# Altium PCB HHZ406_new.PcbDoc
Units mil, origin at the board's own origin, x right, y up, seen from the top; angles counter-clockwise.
Board outline 1050 x 510 mil, 2 copper layers (Top Layer, Bottom Layer); 25 components, 14 nets, 71 pads, 20 vias.
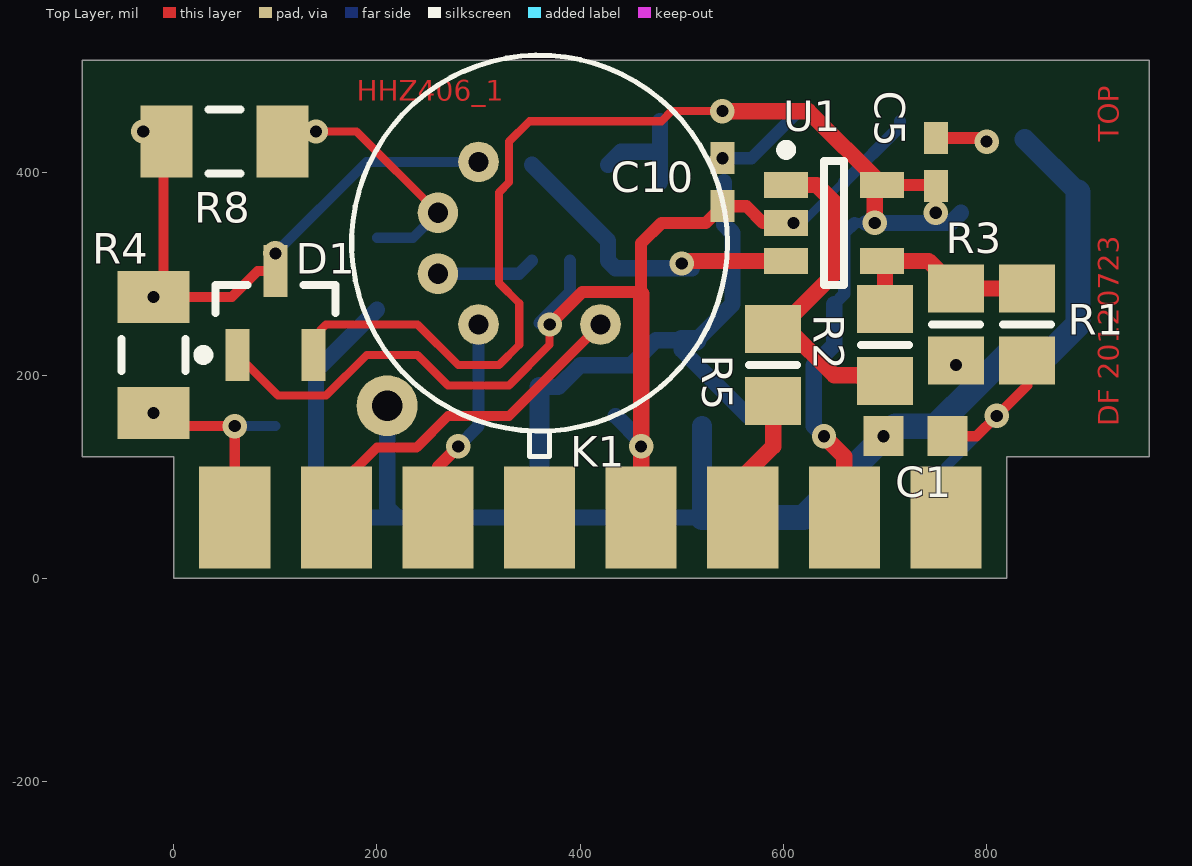
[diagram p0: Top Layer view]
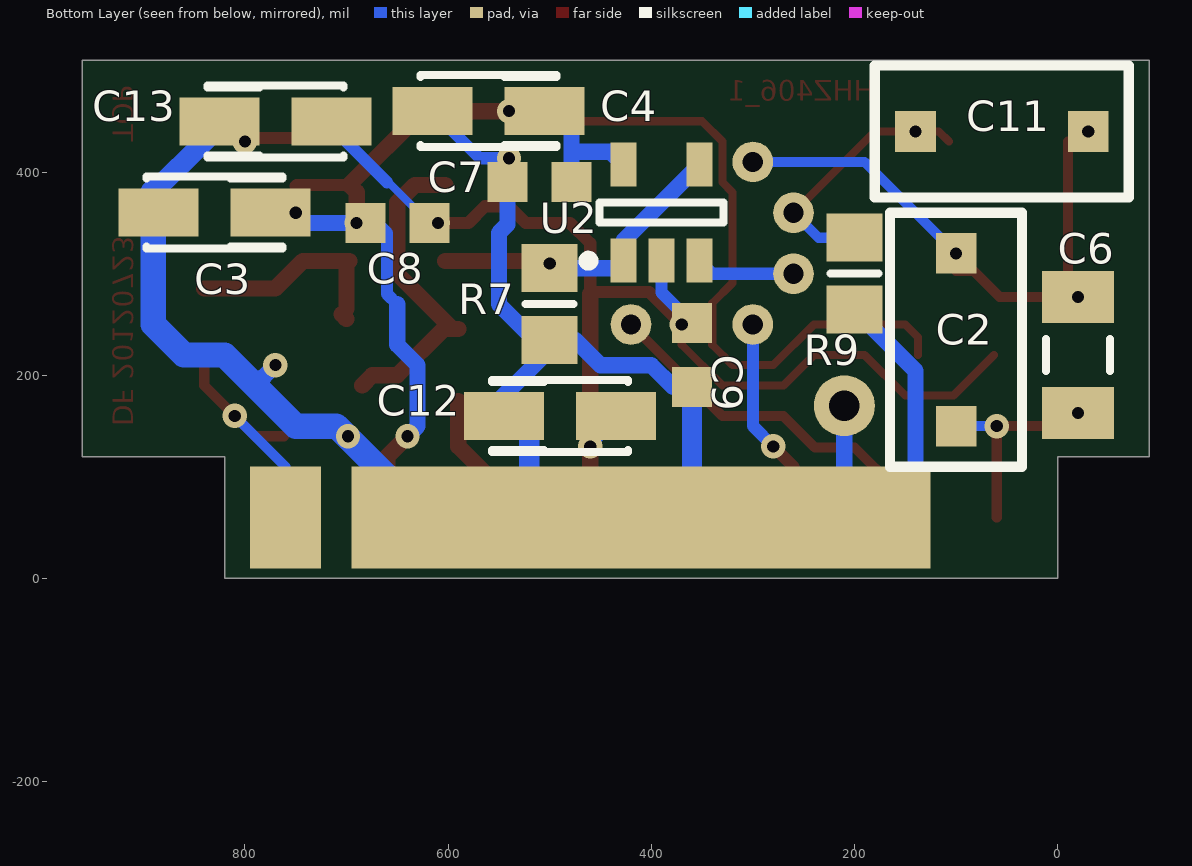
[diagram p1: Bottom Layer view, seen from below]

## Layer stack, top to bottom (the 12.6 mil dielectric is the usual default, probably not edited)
Top Layer: signal copper 1.4
Dielectric: dielectric 12.6, FR-4, Dk 4.8
Bottom Layer: signal copper 1.4

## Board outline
-90,120 -90,510 960,510 960,120 820,120 820,0 0,0 0,120

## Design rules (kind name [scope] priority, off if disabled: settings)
Clearance Clearance_PatchPad [All vs InPadClass('PatchPad')] p1: gap=25 // clearance to pads of within patch area
Clearance PolygonClearanceToNets [InPolygon vs InNet('GATE') OR InNet('U7_FB') OR InNet('U8_FB') OR InNet('U9_FB')] p2: gap=20 // Clearance to special nets, to minimize parasitic capacitance
Clearance PolygonClearance [InPolygon vs IsPad OR IsVia OR IsTrack OR InPoly] p3: gap=10 // Control the distance between polygon pour and other objects
Clearance [All] p4: gap=6
DiffPairsRouting [All] p1: maxlimit=393.7 minlimit=4.92 mostfreqgap=5.91 maxuncoupledlength=500
FabricationTestPointUsage FabricationTestPointUsage_1 [All] p1: valid=0 allowmultiple=FALSE
FabricationTestpoint FabricationTestpoint_1 [All] p1: side=3 testpointundercomponent=TRUE minsize=40 maxsize=100 preferedsize=60 minholesize=0 maxholesize=40 preferedholesize=32 testpointgrid=1 allowsidetop=TRUE allowsidebottom=TRUE usegrid=TRUE gridtolerance=0.01
HoleSize [All] p1: absolutevalues=TRUE maxlimit=236.22 minlimit=12 maxpercent=80.000 minpercent=20.000
HoleSize FabricationTestpoint [All] p2 off: absolutevalues=TRUE maxlimit=100 minlimit=1 maxpercent=80.000 minpercent=20.000
HoleSize FabricationTestPointUsage [All] p3 off: absolutevalues=TRUE maxlimit=100 minlimit=1 maxpercent=80.000 minpercent=20.000
MinimumAnnularRing [All] p1: minimumring=5.91
MinimumSolderMaskSliver [All] p1: minsoldermaskwidth=4
PlaneClearance [All] p1: clearance=19.68
PlaneConnect [All] p1: planeconnectstyle=Relief reliefexpansion=15.75 reliefentries=4 reliefconductorwidth=5.91 reliefairgap=5.91
PolygonConnect PolygonConnect_ViaOrSpecialPad [IsVia OR InPadClass('MountingHole') OR InPadClass('Screen1')] p1: connectstyle=Direct reliefconductorwidth=10 reliefentries=4 polygonreliefangle="90 Angle" // stitched vias and special pads should not have thermal relief
PolygonConnect [All] p2: connectstyle=Relief reliefconductorwidth=5.91 reliefentries=4 polygonreliefangle="90 Angle"
RoutingCorners [All] p1: cornerstyle=45-Degree minsetback=49.21 maxsetback=49.21
RoutingVias [All] p1: holewidth=12 width=24 viastyle="Through Hole" minholewidth=12 minwidth=24 maxholewidth=17.72 maxwidth=29.53
SilkToSilkClearance [All] p1 off: silktosilkclearance=10
SilkscreenOverComponentPads [All] p1 off: minsilkscreentomaskgap=10
SolderMaskExpansion SolderMaskExpansion_Via [IsVia] p1: expansion=0 // Via solder mask expansion
SolderMaskExpansion [All] p2: expansion=2.95
ViasUnderSMD [All] p1: allowed=FALSE
Width [All] p1: maxlimit=393.7 minlimit=6 preferedwidth=6
18 further rules are at their usual default settings.

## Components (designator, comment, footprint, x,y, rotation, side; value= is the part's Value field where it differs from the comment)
C1 "Cap" CAPC1608N 730,140 r0 top
C2 "ThinTrim 9702" "THINTRIM 9702" 100,150 r90 bottom
C3 "Cap Pol1" TC3216-1206 830,360 r0 bottom
C4 "Cap Pol1" TC3216-1206 560,460 r0 bottom
C5 "Cap" CAPC1005N 750,410 r90 top
C6 "Cap" CAPC3216N -20,220 r90 bottom
C7 "Cap" CAPC1608N 510,390 r0 bottom
C8 "Cap" CAPC1608N 650,350 r180 bottom
C9 "Cap" CAPC1608N 360,220 r270 bottom
C10 "Cap" CAPC1005N 540,390 r90 top
C11 "ThinTrim 9702" "THINTRIM 9702" 140,440 r180 bottom
C12 "Cap Pol1" TC3216-1206 490,160 r180 bottom
C13 "Cap Pol1" TC3216-1206 770,450 r180 bottom
D1 "BAS70-04" SOT23_N 100,261.34 r90 top
K1 "412D-SPECIAL" "Teledyne Relay 412 Half 2" 360,330 r180 top
R1 "Res2" RESC2012N 840,250 r90 top
R2 "Res2" RESC2012N 700,230 r270 top
R3 "Res2" RESC2012N 770,250 r90 top
R4 "Res2" RESC3216N -20,220 r90 top
R5 "Res2" RESC2012N 590,210 r90 top
R7 "Res2" RESC2012N 500,270 r90 bottom
R8 "Res2" RESC3216N 50,430 r180 top
R9 "Res2" RESC2012N 200,300 r90 bottom
U1 "LMH6702MF" MF05A_N 650,350 r0 top
U2 "OPA659 DBV" SOT23-5AN 390,360 r90 bottom

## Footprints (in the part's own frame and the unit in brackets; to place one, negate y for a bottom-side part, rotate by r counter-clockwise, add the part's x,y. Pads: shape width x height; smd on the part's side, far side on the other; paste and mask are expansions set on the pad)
CAPC1005N [mm] "Chip Capacitor, Body 1.0x0.5mm, IPC Medium Density"
  rect 0.8x0.6 smd: 1(-0.6,0) 2(0.6,0)
  body extent -0.55,-0.3 0.55,0.3, height 0.6
CAPC1608N [mm] "Chip Capacitor, Body 1.6x0.8mm, IPC Medium Density"
  rect 1x1 smd: 1(-0.8,0) 2(0.8,0)
  body extent -0.87,-0.48 0.87,0.48, height 0.85
CAPC3216N [mm] "Chip Capacitor, Body 3.2x1.6mm, IPC Medium Density"
  rect 1.3x1.8 smd: 1(-1.45,0) 2(1.45,0)
  silkscreen extent -0.4,-0.8 0.4,0.8, body extent -1.7,-0.9 1.7,0.9, height 1.35
MF05A_N [mm] "SOT23, 5-Leads, Body 2.9x1.6mm, Pitch 0.95mm, Lead Span 2.8mm, IPC Medium Density"
  rect 1.1x0.65 smd: 1(-1.2,0.95) 2(-1.2,0) 3(-1.2,-0.95) 4(1.2,-0.95) 5(1.2,0.95)
  silkscreen extent -1.32,-1.55 0.25,1.95, body extent -0.9,-1.55 0.9,1.55, height 1.19
RESC2012N [mm] "Chip Resistor, Body 2.0x1.3mm, IPC Medium Density"
  rect 1.2x1.4 smd: 1(-0.9,0) 2(0.9,0)
  silkscreen extent 0,-0.6 0,0.6, body extent -1.07,-0.7 1.07,0.7, height 0.65
RESC3216N [mm] "Chip Resistor, Body 3.2x1.6mm, IPC Medium Density"
  rect 1.3x1.8 smd: 1(-1.45,0) 2(1.45,0)
  silkscreen extent -0.4,-0.8 0.4,0.8, body extent -1.68,-0.87 1.68,0.87, height 0.71
SOT23-5AN [mm] "SOT23, 5-Leads, Body 2.9x1.6mm, Pitch 0.95mm, Lead Span 2.8mm, IPC Medium Density"
  rect 1.1x0.65 smd: 1(-1.2,0.95) 2(-1.2,0) 3(-1.2,-0.95) 4(1.2,-0.95) 5(1.2,0.95)
  silkscreen extent -1.32,-1.55 0.25,1.95, body extent -0.9,-1.55 0.9,1.55, height 1.45
SOT23_N [mm] "SOT23, 3-Leads, Body 2.9x1.3mm, Pitch 0.95mm, Lead Span 2.3mm, IPC Medium Density"
  rect 1.3x0.6 smd: 1(-1.05,0.95) 2(-1.05,-0.95) 3(1.05,0)
  silkscreen extent -1.17,-1.5 0.7,1.92, body extent -0.7,-1.5 0.7,1.5, height 1.1
TC3216-1206 [mm] "Capacitor, SM Tantalum; Body 3.2 x 1.6 mm (LxW typ)"
  rect 2x1.2 smd: 1(-1.4,0) 2(1.4,0)
  silkscreen extent -1.7,-0.9 1.7,0.9
"Teledyne Relay 412 Half 2" [mil] "Teledyne Relay 412 Half 2"
  round 40 hole 20: 1(-60,80) 5(60,-80) 6(100,-30) 7(100,30) 8(60,80)
  silkscreen extent -185,-185 185,210
"THINTRIM 9702" [mil] "Johanson Thintrim Trimmer Cap 9702 series"
  rect 40x40 smd: 1(0,0) 2(170,0)
  silkscreen extent -40,-65 210,65

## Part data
C1 C5 C6 C7 C8 C9 C10: "Capacitor"
C2 C11: library part "CapVar ThinTrim 9702"
C3 C4 C12 C13: "Polarized Capacitor (Radial)"
D1: "Schottky Barrier Double Diode"
K1: library part TEL412D_2, "Teledyne 412D Half"
R1 R2 R3 R4 R5 R7 R8 R9: "Resistor"
U1: "1.7 GHz, Ultra Low Distortion, Wideband Op Amp, 5-pin SOT-23"
U2: library part OPA659

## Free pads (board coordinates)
  round 60 hole 30: 0(210,170)
  rect 70x100 smd: 1(60,60) 2(160,60) 3(260,60) 4(360,60) 5(460,60) 6(560,60) 7(660,60) 8(760,60)
  rect 70x100 smd far side: 9(760,60)
  rect 570x100 smd far side: 10(410,60)

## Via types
v1: diameter 24, hole 12, Top Layer to Bottom Layer, 20 vias

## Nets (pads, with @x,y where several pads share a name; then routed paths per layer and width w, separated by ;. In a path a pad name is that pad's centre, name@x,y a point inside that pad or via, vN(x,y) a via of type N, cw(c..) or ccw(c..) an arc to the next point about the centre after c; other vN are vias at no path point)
+6V: C3.1 C4.1 C5.1 C7.1 C8.1 D1.2 pad.7 U1.5 U2.5 | length 1510.2
  Top Layer w8: D1.2 137.4,237.4 150,250 240,250 280,210 320,210 340,230 340,270.9 320,290.9 320,380 330,390 330,430 350,450 480,450 490,460 v1(540,460)
  Top Layer w12: U1.5 748.98,387.4 C5.1
  Top Layer w16: v1(540,460) 624.65,460 U1.5 690,380.16 v1(690,350) ; v1(640,140) 660,120 pad.7
  Bottom Layer w10: C8.1@670,350 C8.1
  Bottom Layer w12: 650,270 660,280 660,340 C8.1@670,350
  Bottom Layer w16: U2.5 440.16,420 478.5,420 ; C7.1 478.5,420 ; C4.1@478.5,450 478.5,420 ; v1(640,140) 630,150 630,210 650,230 650,270 ; C8.1 v1(690,350) 764.88,350 C3.1
  other v1: 750,360
-6V: C8.2 C9.1 C10.1 C12.2 C13.2 D1.1 pad.5 U1.2 U2.2 | length 1183.1
  Top Layer w8: D1.1 102.6,180 150,180 190,220 240,220 270,190 330,190 370,230 v1(370,250)
  Top Layer w12: v1(370,250) 402,282 458,282 460,280 460,330 480,350 523.62,350 C10.1 563.62,366.38 580,350 U1.2
  Top Layer w16: pad.5 v1(460,130) 460,280
  Bottom Layer w8: C8.2 658.5,390 660,390
  Bottom Layer w12: C9.1 390,281.5 U2.2 ; 660,390 714.88,444.88 C13.2
  Bottom Layer w16: C12.2 460,134.88 v1(460,130)
  other v1: 610,350
BUF_OUT: R7.2 U1.3 U2.1 U2.4 | length 314.9
  Top Layer w16: v1(500,310) 502.6,312.6 U1.3
  Bottom Layer w16: U2.4 427.4,332.44 U2.1 434.72,305.43 R7.2 R7.2@510,305.43
GND: C1.1 C3.2 C4.2 C5.2 C7.2 C9.2 C10.2 C12.1 C13.1 pad.0 pad.10 R3.1 R7.1 R9.1 | length 2152.6
  Top Layer w12: C5.2 796.38,433.62 v1(800,430)
  Bottom Layer w12: v1(540,413.62) 568.74,413.62 C4.2
  Bottom Layer w16: R9.1 140,204.57 140,50 150,60 pad.10@220,60 ; pad.0 210,70 pad.10@220,60 ; C9.2 378.5,188.5 400,210 450,210 474.57,234.57 R7.1 ; R7.1@500,225.12 C12.1@565.12,160 ; R7.1@514.57,234.57 550,270 550,340 541.5,348.5 C7.2 ; pad.10@520,60 pad.10 pad.10@220,60 ; v1(770,210) 790,190
  Bottom Layer w20: 360,110 C9.2 ; R7.1 R7.1@514.57,234.57 ; pad.10@520,60 C12.1@520,150 ; C13.1@837.56,432.44 C3.2@890,380
  Bottom Layer w25: pad.10@520,60 pad.10@540,60 ; pad.10@560,60 620,60 710,150 750,150 790,190 820,220 860,220 890,250 C3.2@890,380
  other v1: 698.5,140
IN1: C2.2 C6.2 C11.2 D1.3 K1.5 R4.2 R8.2 | length 524.9
  Top Layer w10: R8.2@-10,430 -10,287.09 v1(-20,277.09) 57.09,277.09 82.68,302.68 D1.3
  Bottom Layer w10: v1(100,320) 190,410 K1.5
  other v1: -30,440
NetC2_1: C2.1 C6.1 pad.1 R4.1 | length 224.5
  Top Layer w10: R4.1@-13.54,156.46 -7.09,150 v1(60,150) pad.1
  Bottom Layer w8: v1(-20,162.91) C6.1@-7.09,150
  Bottom Layer w10: v1(60,150) C2.1
NetC11_1: C11.1 K1.6 R8.1 R9.2 | length 260.4
  Top Layer w8: R8.1 117.09,440 v1(140,440) 180,440 K1.6
  Bottom Layer w10: R9.2 235.43,335.43 K1.6
NetK1_7: K1.7 U2.3 | length 97.9
  Bottom Layer w12: K1.7 339.84,300 U2.3
NetR1_2: R1.2 R2.1 R3.2 U1.4 | length 208.8
  Top Layer w16: R2.1@700,255.43 R2.1@704.57,260 ; R2.1 700,309.84 U1.4 742.83,312.6 R3.2 R1.2
NetR2_2: R2.2 R5.2 U1.1 | length 319.1
  Top Layer w16: R5.2 R5.2@595.43,245.43 ; U1.1 632.6,387.4 650,370 650,300 R5.2@595.43,245.43 ; R2.2@684.57,190 674.57,200 650,200 604.57,245.43 R5.2@595.43,245.43
OFFSET: C1.2 pad.9 R1.1 | length 244.5
  Top Layer w10: C1.2 790,140 v1(810,160) 840,190 R1.1
  Bottom Layer w10: pad.9 760,110 v1(810,160)
OUT: pad.6 R5.1 | length 127
  Top Layer w16: pad.6 560,100 590,130 R5.1
REL+: K1.1 pad.2 | length 355.7
  Top Layer w10: pad.2 160,89 200,129 239,129 270,160 330,160 K1.1
REL-: K1.8 pad.3 | length 206.6
  Top Layer w12: pad.3 260,110 v1(280,130)
  Bottom Layer w12: v1(280,130) 300,150 K1.8

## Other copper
Top Layer:
  text "HHZ406_1" at 180,470 h20
  text "TOP" at 930,430 h20 r90
  text "DF 20120723" at 930,150 h20 r90

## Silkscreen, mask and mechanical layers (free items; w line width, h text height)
Mechanical 2:
  the board outline again, w10
Drill Drawing:
  text ".LEGEND" at 170,-2352.09 h60
  text "Drill Drawing." at 170,-2452.09 h60

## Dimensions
1090,505.05 to 1090,-4.95 on Mechanical 2
-99.94,-70 to 960.06,-50 on Mechanical 2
